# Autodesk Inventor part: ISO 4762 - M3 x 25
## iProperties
Created: 2008-01
Part Number: ISO 4762 - M3 x 25
Material: Stainless Steel, 440C
Description: Hexagon Socket Head Cap Screw
Document SubType Name: Modeling
Standard: ISO 4762
Designer: latalom
Standard Revision: Fourth edition 2004-03-01
Standards Organization: ISO
Language: en-US
Size Designation: M3 x 25
Categories: <MemberInstance><Categories><Category DisplayName="Fasteners" InternalName="e4da775c-781d-43d5-af7c-5136215cf5a6" Mnemonic="FSTN"><Category DisplayName="Bolts"
Density: 7.75 g/cm^3
IsCustomPart: 0
Author: latalom
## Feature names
1. Body [Revolution]
2. Slot [Extrusion]
3. Fillet1
4. Chamfer1
5. Fillet2
